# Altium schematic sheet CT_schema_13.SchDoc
size 146 x 119 mm
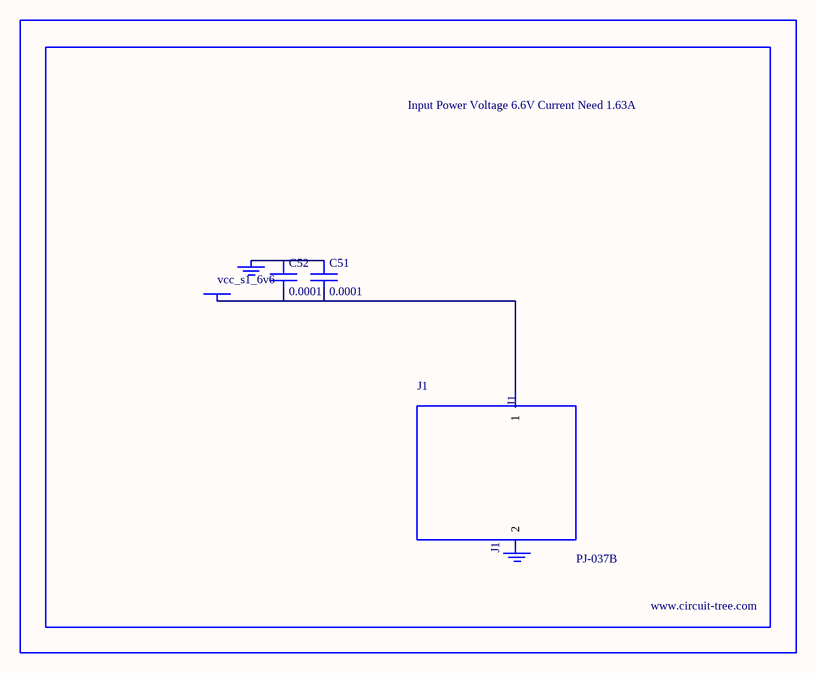
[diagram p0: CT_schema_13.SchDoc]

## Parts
BORDER12  (no value)
C51  0.0001  [EXV-9H]
C52  0.0001  [EXV-9H]
GND_INSTANCE_12_0  (no value)
GND_INSTANCE_12_1  (no value)
J1  PJ-037B  [PJ-037B_PACKAGE]
POWER_INSTANCE_12_0  vcc_s1_6v6

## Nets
NetC51_1: C51.1 C52.1 GND_INSTANCE_12_0.0(GND)
NetC51_2: C51.2 C52.2 J1.1 POWER_INSTANCE_12_0.0(PWR)

Not connected (* = marked no-connect by the designer): GND_INSTANCE_12_1 0(GND); J1 2

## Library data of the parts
BORDER12 = BORDER_PAGE12
C51 C52 = EDK107M035A9HAA
GND_INSTANCE_12_0 GND_INSTANCE_12_1 = GND
POWER_INSTANCE_12_0 = PWR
